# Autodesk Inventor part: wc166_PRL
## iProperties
Shininess: 64.0
Length Units: 11272
Angle Units: 11279
Time Units: 11290
Mass Units: 11286
Length Display Precision: 3
Angle Display Precision: 2
Compacted: True
Part Number: wc166_PRL
Document SubType Name: Modeling
Created: 2004-08
Designer: John Blackburn
Manufacturer: Standard
Standards Organization: Custom
Material: Phenolic
Density: 0.0
Volumn: 0.0
Area: 0.0
PropertySet Name: Model Information
Control State: 0
Master: False
Checked Out: False
Author: John Blackburn
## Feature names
1. Revolution1
